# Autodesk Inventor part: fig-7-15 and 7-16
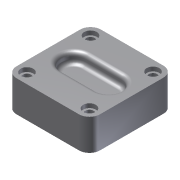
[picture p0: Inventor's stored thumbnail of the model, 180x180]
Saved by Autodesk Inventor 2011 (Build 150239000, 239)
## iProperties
Shininess: 77.0
Angle Display Precision: 2
Document Length Units: 11269
Document Angle Units: 11279
Document Time Units: 11290
Document Mass Units: 11283
Document Length Units Precision: 3
Document Angle Units Precision: 2
Created: 2001-12
Part Number: fig-7-15 and 7-16
Document SubType Name: Modeling
Designer: Renu Muthoo
Density: 1 g/cm^3
Density: 0.0
Volumn: 0.0
Area: 0.0
PropertySet Name: Model Information
Control State: 0
Master: False
Checked Out: False
Author: Renu Muthoo
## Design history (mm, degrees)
sketch "Sketch1"
  geometry: L1 (-20, 20)-(20, 20); L2 (20, 20)-(20, -20.5); L3 (20, -20.5)-(-20, -20.5); L4 (-20, -20.5)-(-20, 20); 1 further point
  constraints: 8 end point, 2 parallel, 1 horizontal, 1 perpendicular, 1 other
  dimensions: "d0" = 40 distance of L1.start L1.end; "d1" = 40.5 distance of L3.end L1.start; "d100" = 20 distance from line of L4 point (0, 0); "d101" = 20 distance from line of L1 point (0, 0)
extrude "Extrusion1" new body sketch "Sketch1" distance "d2" = 15; taper "d3" = 0 deg
workplane "Work Plane1"
workplane "Work Plane2"
workplane "Work Plane3"
workplane "Work Plane4"
fillet "Fillet1" dims "d32" = 5
hole "Hole3" diameter "d66" = 4; stored, may be unused: countersink angle "d70" = 90 deg, drill point angle "d72" = 118 deg; dims "d64" = 10, "d65" = 10, "d67" = 6, "d68" = 6, "d69" = 2, "d71" = 8
hole "Hole4" diameter "d75" = 4; stored, may be unused: countersink angle "d79" = 90 deg, drill point angle "d81" = 118 deg; dims "d73" = 10, "d74" = 10, "d76" = 6, "d77" = 6, "d78" = 2, "d80" = 8
hole "Hole5" diameter "d84" = 4; stored, may be unused: countersink angle "d88" = 90 deg, drill point angle "d90" = 118 deg; dims "d82" = 10, "d83" = 10, "d85" = 6, "d86" = 6, "d87" = 2, "d89" = 8
hole "Hole6" diameter "d93" = 4; stored, may be unused: countersink angle "d97" = 90 deg, drill point angle "d99" = 118 deg; dims "d91" = 10, "d92" = 10, "d94" = 6, "d95" = 6, "d96" = 2, "d98" = 8
fillet "Fillet2" dims "d61" = 2
body "Solid1"
sketch "Sketch8"
  geometry: L1 (-9.844, 1.64)-(1.983, -10.187); L2 (10.469, -1.701)-(-1.358, 10.126); A1 r 6 centre (-5.601, 5.883) between (-1.358, 10.126) and (-9.844, 1.64); A2 r 6 centre (6.226, -5.944) between (1.983, -10.187) and (10.469, -1.701)
  constraints: 4 end point, 4 point on circle, 4 tangent, 2 centre point, 1 parallel
  dimensions: "d29" = 6 radius of A2
extrude "Extrusion2" cut sketch "Sketch8" distance "d30" = 5; taper "d31" = 0 deg
